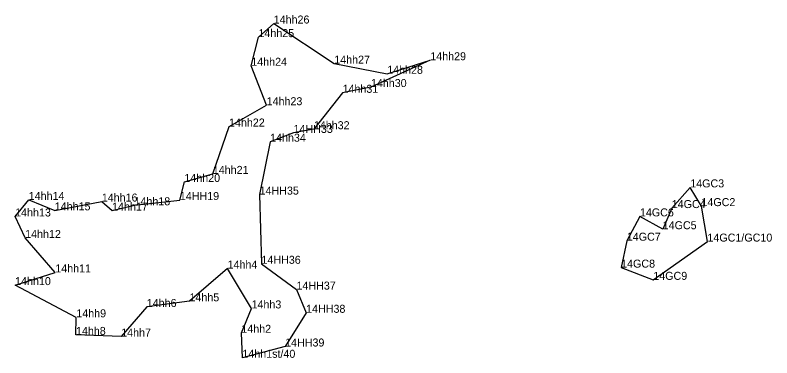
# Model space of a CAD drawing. Extents: x 2072529 to 2267990, y 436423 to 470008.
# Drawn here: x 2258181.8 to 2258654.6, y 441582.5 to 441796.9 of the extents above; entities that cross this region are included whole.
import ezdxf

# ---------------------------------------------------------------- set-up
doc = ezdxf.new("R2010")
doc.units = 0
doc.layers.add('Level 3', color=7, linetype='Continuous')
doc.layers.add('Old_Level_52', color=7, linetype='Continuous')

msp = doc.modelspace()

# ---------------------------------------------------------------- linework, layer by layer
at = {"layer": 'Level 3'}
for p, q in [((2258343.399, 441791.6), (2258343.399, 441791.6)), ((2258333.868, 441783.101), (2258333.868, 441783.101)), ((2258441.227, 441768.649), (2258441.227, 441768.649)), ((2258329.379, 441765.18), (2258329.379, 441765.18)), ((2258381.22, 441766.513), (2258381.22, 441766.513)), ((2258414.318, 441760.176), (2258414.318, 441760.176)), ((2258404.135, 441751.895), (2258404.135, 441751.895)), ((2258386.413, 441748.285), (2258386.413, 441748.285)), ((2258338.974, 441740.52), (2258338.974, 441740.52)), ((2258315.478, 441727.206), (2258315.478, 441727.206)), ((2258355.761, 441723.218), (2258355.761, 441723.218)), ((2258368.48, 441725.526), (2258368.48, 441725.526)), ((2258341.151, 441717.707), (2258341.151, 441717.707)), ((2258305.355, 441697.59), (2258305.355, 441697.59)), ((2258287.581, 441692.559), (2258287.581, 441692.559)), ((2258603.652, 441689.144), (2258603.652, 441689.144)), ((2258334.561, 441684.629), (2258334.561, 441684.629)), ((2258190.326, 441681.312), (2258190.326, 441681.312)), ((2258235.988, 441680.283), (2258235.988, 441680.283)), ((2258284.738, 441681.219), (2258284.738, 441681.219)), ((2258206.577, 441674.788), (2258206.577, 441674.788)), ((2258242.401, 441674.641), (2258242.401, 441674.641)), ((2258256.416, 441677.958), (2258256.416, 441677.958)), ((2258592.094, 441676.209), (2258592.094, 441676.209)), ((2258610.626, 441677.419), (2258610.626, 441677.419)), ((2258181.837, 441670.951), (2258181.837, 441670.951)), ((2258572.219, 441671.006), (2258572.219, 441671.006)), ((2258586.438, 441662.974), (2258586.438, 441662.974)), ((2258188.101, 441657.498), (2258188.101, 441657.498)), ((2258564.008, 441655.804), (2258564.008, 441655.804)), ((2258614.395, 441655.245), (2258614.395, 441655.245)), ((2258335.731, 441641.36), (2258335.731, 441641.36)), ((2258314.568, 441638.377), (2258314.568, 441638.377)), ((2258560.467, 441638.968), (2258560.467, 441638.968)), ((2258206.923, 441636.001), (2258206.923, 441636.001)), ((2258181.829, 441628.035), (2258181.829, 441628.035)), ((2258580.564, 441631.325), (2258580.564, 441631.325)), ((2258357.618, 441625.237), (2258357.618, 441625.237)), ((2258290.761, 441617.899), (2258290.761, 441617.899)), ((2258264.08, 441614.376), (2258264.08, 441614.376)), ((2258329.538, 441613.456), (2258329.538, 441613.456)), ((2258220.055, 441607.879), (2258220.055, 441607.879)), ((2258363.636, 441610.724), (2258363.636, 441610.724)), ((2258219.858, 441596.875), (2258219.858, 441596.875)), ((2258248.102, 441595.855), (2258248.102, 441595.855)), ((2258323.171, 441598.207), (2258323.171, 441598.207)), ((2258350.545, 441589.643), (2258350.545, 441589.643)), ((2258323.813, 441582.6), (2258323.813, 441582.6))]:
    msp.add_line(p, q, dxfattribs=at)
at = {"layer": 'Old_Level_52'}
for points in [[(2258323.813, 441582.6), (2258323.171, 441598.207), (2258329.538, 441613.456), (2258314.568, 441638.377), (2258290.761, 441617.899), (2258264.08, 441614.376), (2258248.102, 441595.855), (2258219.858, 441596.875), (2258220.055, 441607.879), (2258181.829, 441628.035), (2258206.923, 441636.001), (2258188.101, 441657.498), (2258181.837, 441670.951), (2258190.326, 441681.312), (2258206.577, 441674.788), (2258235.988, 441680.283), (2258242.401, 441674.641), (2258256.416, 441677.958), (2258284.738, 441681.219), (2258287.581, 441692.559), (2258305.355, 441697.59), (2258315.478, 441727.206), (2258338.974, 441740.52), (2258329.379, 441765.18), (2258333.868, 441783.101), (2258343.399, 441791.6), (2258381.22, 441766.513), (2258414.318, 441760.176), (2258441.227, 441768.649), (2258404.135, 441751.895), (2258386.413, 441748.285), (2258368.48, 441725.526), (2258355.761, 441723.218), (2258341.151, 441717.707), (2258334.561, 441684.629), (2258335.731, 441641.36), (2258357.618, 441625.237), (2258363.636, 441610.724), (2258350.545, 441589.643)], [(2258614.395, 441655.245), (2258610.626, 441677.419), (2258603.652, 441689.144), (2258592.094, 441676.209), (2258586.438, 441662.974), (2258572.219, 441671.006), (2258564.008, 441655.804), (2258560.467, 441638.968), (2258580.564, 441631.325)]]:
    msp.add_lwpolyline(points, close=True, dxfattribs=at)

# ---------------------------------------------------------------- texts
for s, p in [('14hh26', (2258343.399, 441791.6)), ('14hh25', (2258333.868, 441783.101)), ('14hh29', (2258441.227, 441768.649)), ('14hh24', (2258329.379, 441765.18)), ('14hh27', (2258381.22, 441766.513)), ('14hh28', (2258414.318, 441760.176)), ('14hh30', (2258404.135, 441751.895)), ('14hh31', (2258386.413, 441748.285)), ('14hh23', (2258338.974, 441740.52)), ('14hh22', (2258315.478, 441727.206)), ('14hh32', (2258368.48, 441725.526)), ('14HH33', (2258355.761, 441723.218)), ('14hh34', (2258341.151, 441717.707)), ('14hh21', (2258305.355, 441697.59)), ('14hh20', (2258287.581, 441692.559)), ('14GC3', (2258603.652, 441689.144)), ('14HH35', (2258334.561, 441684.629)), ('14hh14', (2258190.326, 441681.312)), ('14hh16', (2258235.988, 441680.283)), ('14HH19', (2258284.738, 441681.219)), ('14hh15', (2258206.577, 441674.788)), ('14hh17', (2258242.401, 441674.641)), ('14hh18', (2258256.416, 441677.958)), ('14GC4', (2258592.094, 441676.209)), ('14GC2', (2258610.626, 441677.419)), ('14hh13', (2258181.837, 441670.951)), ('14GC6', (2258572.219, 441671.006)), ('14GC5', (2258586.438, 441662.974)), ('14hh12', (2258188.101, 441657.498)), ('14GC7', (2258564.008, 441655.804)), ('14GC1/GC10', (2258614.395, 441655.245)), ('14HH36', (2258335.731, 441641.36)), ('14hh11', (2258206.923, 441636.001)), ('14hh4', (2258314.568, 441638.377)), ('14GC8', (2258560.467, 441638.968)), ('14GC9', (2258580.564, 441631.325)), ('14hh10', (2258181.829, 441628.035)), ('14HH37', (2258357.618, 441625.237)), ('14hh5', (2258290.761, 441617.899)), ('14hh6', (2258264.08, 441614.376)), ('14hh3', (2258329.538, 441613.456)), ('14hh9', (2258220.055, 441607.879)), ('14HH38', (2258363.636, 441610.724)), ('14hh2', (2258323.171, 441598.207)), ('14hh8', (2258219.858, 441596.875)), ('14hh7', (2258248.102, 441595.855)), ('14HH39', (2258350.545, 441589.643)), ('14hh1st/40', (2258323.813, 441582.6))]:
    msp.add_text(s, height=5).set_placement(p)

doc.saveas('drawing.dxf')
